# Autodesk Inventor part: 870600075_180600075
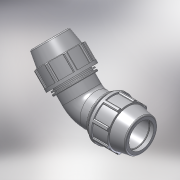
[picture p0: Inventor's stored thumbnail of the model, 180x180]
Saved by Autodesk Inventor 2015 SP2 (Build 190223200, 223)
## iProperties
Created: 2017-02
Part Number: 870600075_180600075
Material: PVC-Piping
Description: PLASSON 45° ELBOW 75-75
Document SubType Name: Modeling
Designer: KIM
Mass: 92.6774 g
Surface Area: 199.44 cm^2
Volume: 66.1981 cm^3
Density: 1.4 g/cm^3
Appearance: Smooth - White
Author: Кирилл
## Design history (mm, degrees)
derived "87060.ipt"
feature "Solid1::87060.ipt"
tag "TaggingFeature1"
body "Solid1"
other parameters: "d2" = 75, "d4" = 13.25, "d5" = 39.75, "d7" = 132, "d9" = 22.71429, "d11" = 5.3, "d13" = 120 deg, "d14" = 97.5, "d15" = 10 deg, "d16" = 114.84, "d18" = 3.75, "d19" = 35 deg, "d20" = 17.5 deg, "d21" = 122.76, "d23" = 0, "d25" = 360 deg, "d27" = 2.64, "d33" = 1.5, "d42" = 54.06, "d43" = 3.96, "d46" = 1.5, "d51" = 159, "d59" = 135 deg, "d63" = 137, "d64" = 67.5, "d67" = 99, "d68" = 9.54, "d70" = 45 deg, "d72" = 8.8, "d73" = 0, "d75" = 135 deg, "d77" = 112.5432, "d78" = 3.18, "d_" = 75, "E_" = 132, "A_" = 159, "l_" = 137
